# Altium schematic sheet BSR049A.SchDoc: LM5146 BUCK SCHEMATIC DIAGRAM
size 431 x 279 mm; Date: Not shown in title block; ApprovedBy: Not shown in title block; CheckedBy: Not shown in title block; Author: Not shown in title block; CompanyName: Not shown in title block; DrawnBy: K Nielson; Engineer: Not shown in title block; Organization: Not shown in title block; Address1: Not shown in title block; Address2: Not shown in title block; Address3: Not shown in title block; Address4: Not shown in title block; DocumentNumber: 1; Revision: Use project parameter SCH_Rev; SheetNumber: 1; SheetTotal: 2; PageSetup: Record=PageOptions¦CenterHorizontal=True¦CenterVertical=True¦PrintScale=0.96¦XCorrection=1.00¦YCorrection=1.00¦PrintKind=0¦BorderSize=5000000¦LeftOffset=0¦BottomOffset=0¦Orientation=2¦PaperLength=1000¦PaperWidth=1000¦Scale=100¦PaperSource=15¦PrintQuality=-3¦MediaType=1¦DitherType=10¦PrintScaleMode=1¦PaperKind=11x17¦PaperIndex=17
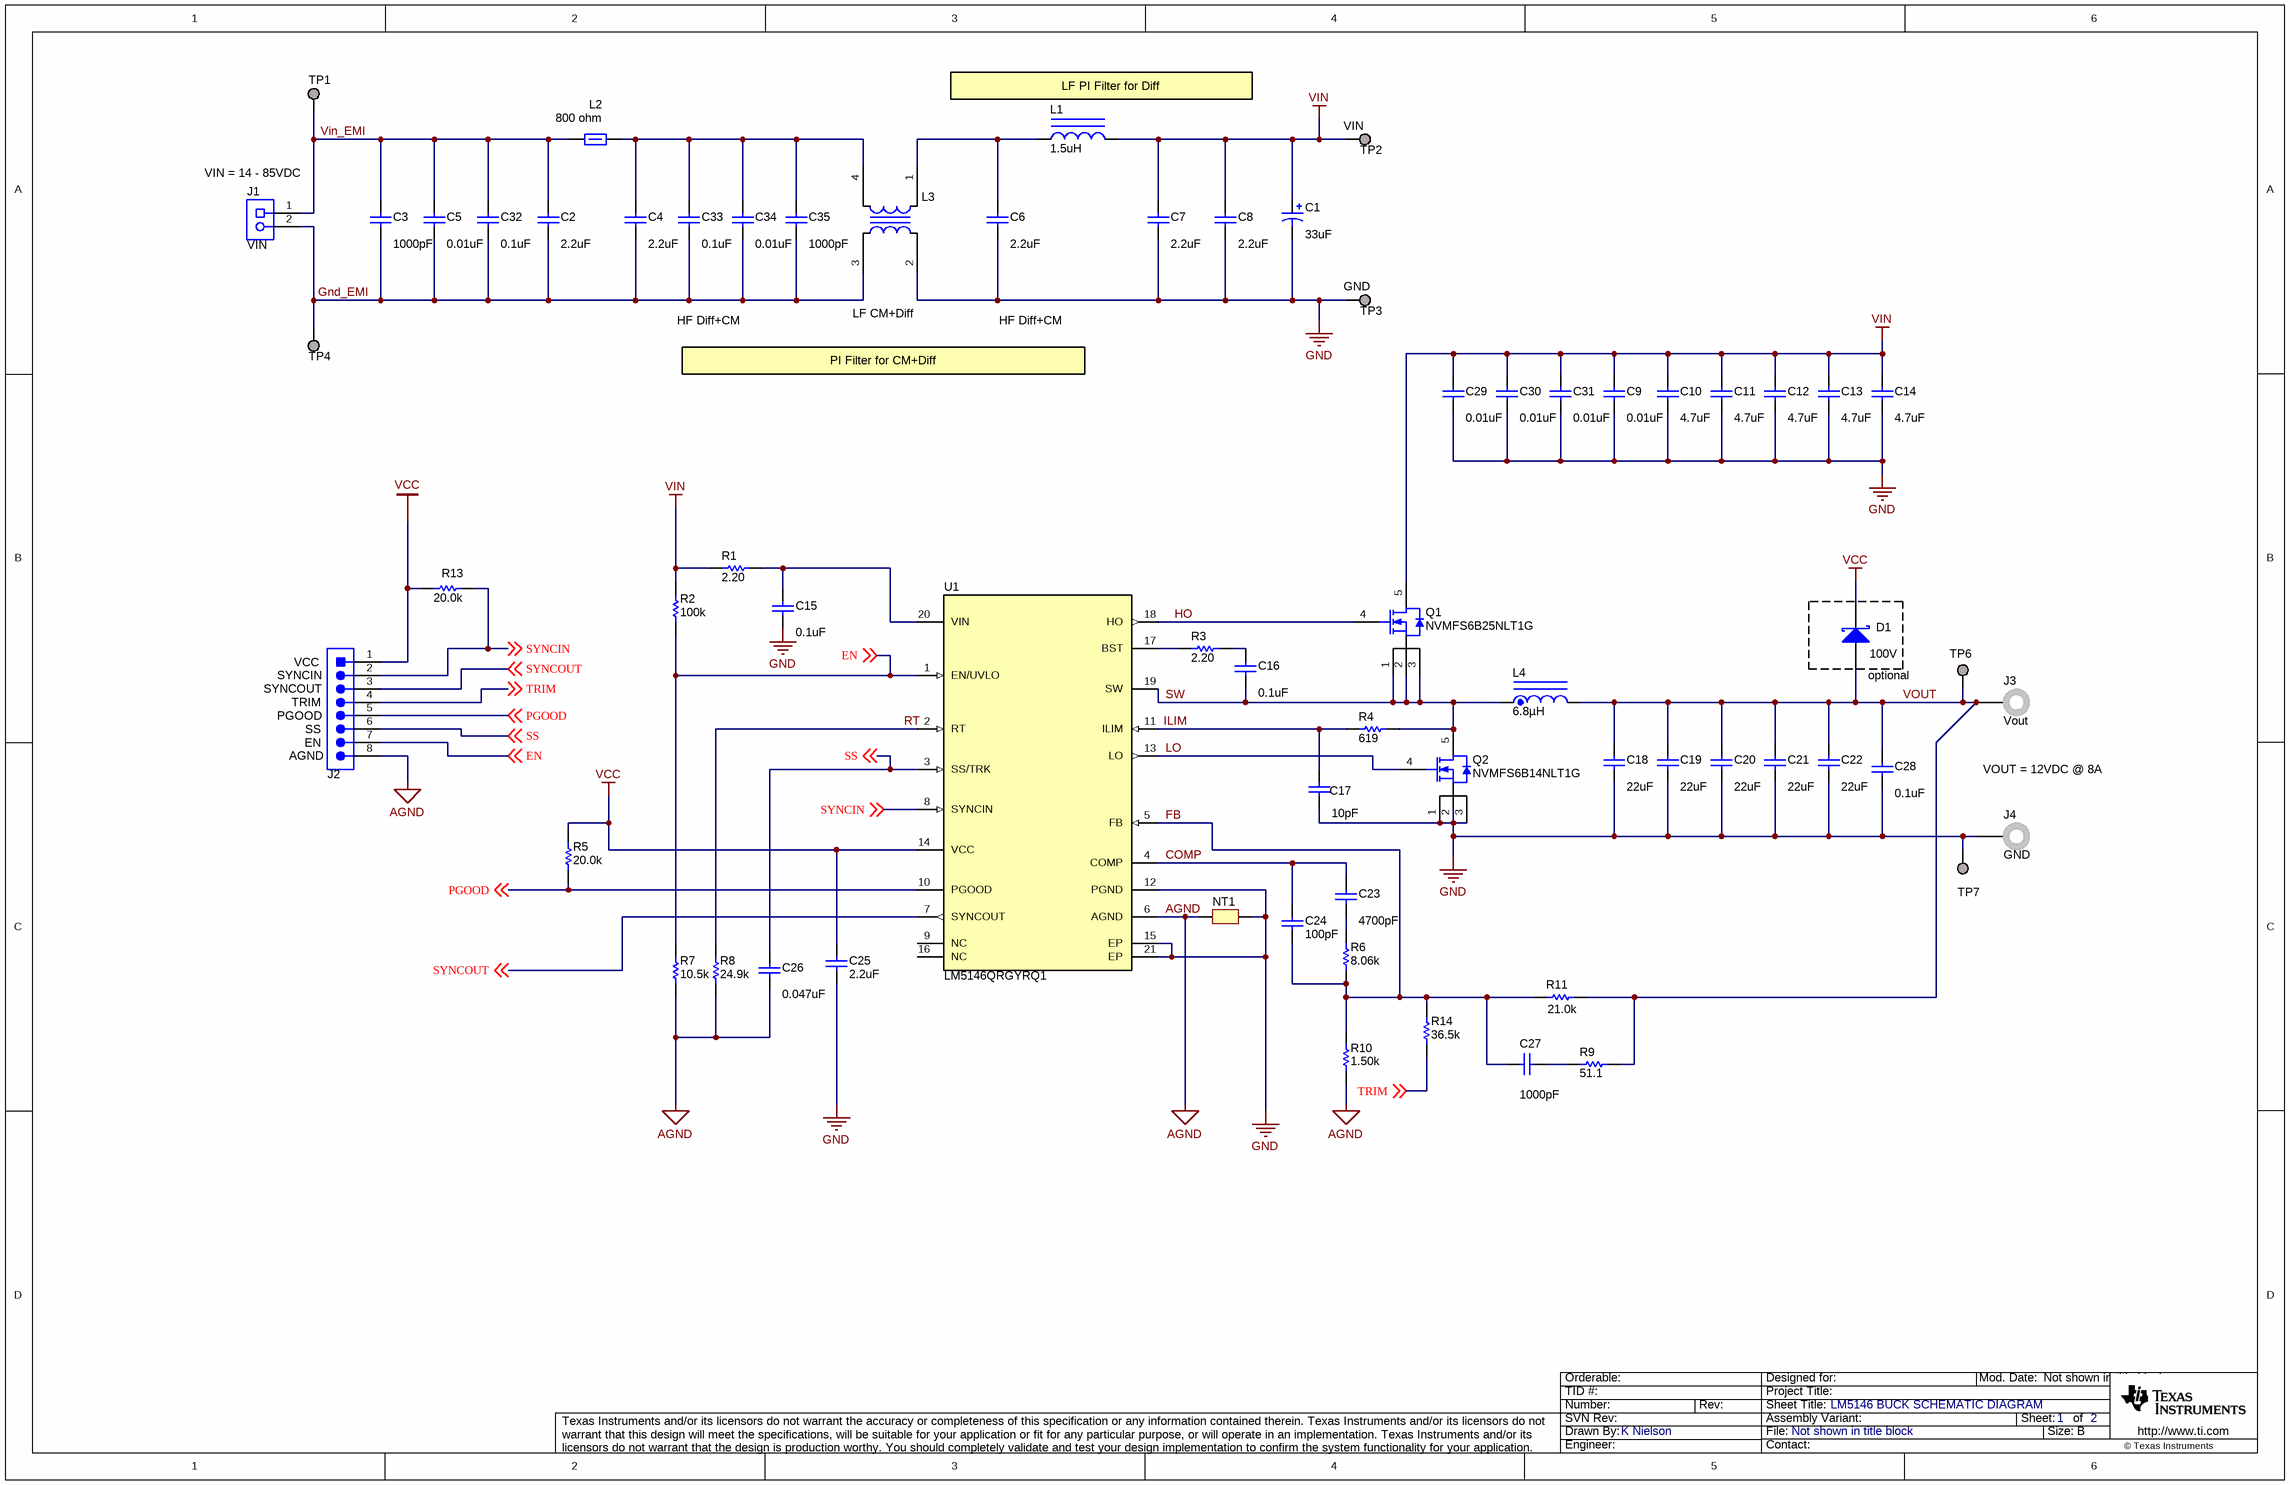
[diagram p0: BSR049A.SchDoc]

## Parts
C1  ValueDisplayed: 33uF  [SM_RADIAL_G]  (hidden comment: EEE-FK2A330P)
C2  ValueDisplayed: 2.2uF  [1210_250]  (hidden comment: CGA6N3X7R2A225K230AB)
C3  ValueDisplayed: 1000pF  [0603L]  (hidden comment: CGA3E2X7R2A102K080AA)
C4  ValueDisplayed: 2.2uF  [1210_250]  (hidden comment: CGA6N3X7R2A225K230AB)
C5  ValueDisplayed: 0.01uF  [0603L]  (hidden comment: GRM188R72A103KA01D)
C6  ValueDisplayed: 2.2uF  [1210_250]  (hidden comment: CGA6N3X7R2A225K230AB)
C7  ValueDisplayed: 2.2uF  [1210_250]  (hidden comment: CGA6N3X7R2A225K230AB)
C8  ValueDisplayed: 2.2uF  [1210_250]  (hidden comment: CGA6N3X7R2A225K230AB)
C9  ValueDisplayed: 0.01uF  [0603L]  (hidden comment: GRM188R72A103KA01D)
C10  ValueDisplayed: 4.7uF  [1210]  (hidden comment: C3225X7S2A475K200AE)
C11  ValueDisplayed: 4.7uF  [1210]  (hidden comment: C3225X7S2A475K200AE)
C12  ValueDisplayed: 4.7uF  [1210]  (hidden comment: C3225X7S2A475K200AE)
C13  ValueDisplayed: 4.7uF  [1210]  (hidden comment: C3225X7S2A475K200AE)
C14  ValueDisplayed: 4.7uF  [1210]  (hidden comment: C3225X7S2A475K200AE)
C15  ValueDisplayed: 0.1uF  [0603L]  (hidden comment: CGA3E3X7S2A104K080AB)
C16  ValueDisplayed: 0.1uF  [0603L]  (hidden comment: CGA3E3X7S2A104K080AB)
C17  ValueDisplayed: 10pF  [0603L]  (hidden comment: 885012006073)
C18  ValueDisplayed: 22uF  [1210_270]  (hidden comment: TMK325B7226KMHT)
C19  ValueDisplayed: 22uF  [1210_270]  (hidden comment: TMK325B7226KMHT)
C20  ValueDisplayed: 22uF  [1210_270]  (hidden comment: TMK325B7226KMHT)
C21  ValueDisplayed: 22uF  [1210_270]  (hidden comment: TMK325B7226KMHT)
C22  ValueDisplayed: 22uF  [1210_270]  (hidden comment: TMK325B7226KMHT)
C23  ValueDisplayed: 4700pF  [0402]  (hidden comment: GRM155R71C472KA01D)
C24  ValueDisplayed: 100pF  [0402]  (hidden comment: CGA2B2C0G1H101J050BA)
C25  ValueDisplayed: 2.2uF  [0805_HV]  (hidden comment: GRM21BR71E225KA73L)
C26  ValueDisplayed: 0.047uF  [0402]  (hidden comment: C1005X7R1C473K050BC)
C27  ValueDisplayed: 1000pF  [0402]  (hidden comment: CGA2B2X7R1H102K050BA)
C28  ValueDisplayed: 0.1uF  [0603L]  (hidden comment: CGA3E3X7S2A104K080AB)
C29  ValueDisplayed: 0.01uF  [0603L]  (hidden comment: GRM188R72A103KA01D)
C30  ValueDisplayed: 0.01uF  [0603L]  (hidden comment: GRM188R72A103KA01D)
C31  ValueDisplayed: 0.01uF  [0603L]  (hidden comment: GRM188R72A103KA01D)
C32  ValueDisplayed: 0.1uF  [0603L]  (hidden comment: CGA3E3X7S2A104K080AB)
C33  ValueDisplayed: 0.1uF  [0603L]  (hidden comment: CGA3E3X7S2A104K080AB)
C34  ValueDisplayed: 0.01uF  [0603L]  (hidden comment: GRM188R72A103KA01D)
C35  ValueDisplayed: 1000pF  [0603L]  (hidden comment: CGA3E2X7R2A102K080AA)
D1  100V  [SOD-523]
J1  VIN  [Phoenix_1984617]
J2  TSW-108-07-G-S  [TSW-108-07-G-S]  (value not drawn)
J3  Vout  [Keystone575-8]
J4  GND  [Keystone575-8]
L1  ValueDisplayed: 1.5uH  [VCMT063T]  (hidden comment: VCMT063T-1R5MN5)
L2  800 ohm  [2220_390]
L3  ACM12V-701-2PL-TL00  [TDK_ACM12V]  (value not drawn)
L4  ValueDisplayed: 6.8µH  [VCHA105D]  (hidden comment: VCHA105D-6R8MS6)
NT1  net tie  [Net-Tie_10mil]  (value not drawn)  (net tie, no BOM)
Q1  NVMFS6B25NLT1G  [SO-8FL]
Q2  NVMFS6B14NLT1G  [SO-8FL]
R1  ValueDisplayed: 2.20  [0603L]  (hidden comment: ERJ-3RQF2R2V)
R2  ValueDisplayed: 100k  [0603]  (hidden comment: CRCW0603100KFKEA)
R3  ValueDisplayed: 2.20  [0603L]  (hidden comment: ERJ-3RQF2R2V)
R4  ValueDisplayed: 619  [0402]  (hidden comment: CRCW0402619RFKED)
R5  ValueDisplayed: 20.0k  [0402]  (hidden comment: CRCW040220K0FKED)
R6  ValueDisplayed: 8.06k  [0402]  (hidden comment: CRCW04028K06FKED)
R7  ValueDisplayed: 10.5k  [0402]  (hidden comment: CRCW040210K5FKED)
R8  ValueDisplayed: 24.9k  [0402]  (hidden comment: CRCW040224K9FKED)
R9  ValueDisplayed: 51.1  [0402]  (hidden comment: CRCW040251R1FKED)
R10  ValueDisplayed: 1.50k  [0402]  (hidden comment: CRCW04021K50FKED)
R11  ValueDisplayed: 21.0k  [0402]  (hidden comment: CRCW040221K0FKED)
R13  ValueDisplayed: 20.0k  [0603L]  (hidden comment: CRCW060320K0FKEA)
R14  ValueDisplayed: 36.5k  [0402]  (hidden comment: CRCW040236K5FKED)
TP1  5017  [Keystone_5017]  (value not drawn)
TP2  VIN  [Keystone_5017]
TP3  GND  [Keystone_5017]
TP4  GND  [Keystone_5017]  (value not drawn)
TP6  GND  [Keystone_5017]  (value not drawn)
TP7  GND  [Keystone_5017]  (value not drawn)
U1  LM5146QRGYRQ1  [RGY0020B]

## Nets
AGND: C26.1 J2.8 NT1.1 R7.1 R8.2 R10.1 U1.6(AGND)
GND: C1.2(-) C6.2 C7.2 C8.2 C9.2 C10.2 C11.2 C12.2 C13.2 C14.2 C15.2 C17.2 C18.2 C19.2 C20.2 C21.2 C22.2 C25.2 C28.2 C29.2 C30.2 C31.2 J4.1 L3.2 NT1.2 Q2.1(S) Q2.2(S) Q2.3(S) TP3.1 TP7.1 U1.12(PGND) U1.15(EP) U1.21(EP)
VCC: C25.1 D1.1(K) J2.1 R5.1 R13.1 U1.14(VCC)
VIN: C1.1(+) C7.1 C8.1 C9.1 C10.1 C11.1 C12.1 C13.1 C14.1 C29.1 C30.1 C31.1 L1.2 Q1.5(D) R1.1 R2.1 TP2.1
COMP: C23.1 C24.1 U1.4(COMP)
EN: J2.7 R2.2 R7.2 U1.1(EN/UVLO) ; off-sheet EN
FB: C24.2 C27.2 R6.1 R10.2 R11.2 R14.2 U1.5(FB)
Gnd_EMI: C2.2 C3.2 C4.2 C5.2 C32.2 C33.2 C34.2 C35.2 J1.2 L3.3 TP4.1
HO: Q1.4(G) U1.18(HO)
ILIM: C17.1 R4.1 U1.11(ILIM)
LO: Q2.4(G) U1.13(LO)
PGOOD: J2.5 R5.2 U1.10(PGOOD) ; off-sheet PGOOD
RT: R8.1 U1.2(RT)
SS: C26.2 J2.6 U1.3(SS/TRK) ; off-sheet SS
SW: C16.2 L4.1 Q1.1(S) Q1.2(S) Q1.3(S) Q2.5(D) R4.2 U1.19(SW)
SYNCIN: J2.2 R13.2 U1.8(SYNCIN) ; off-sheet SYNCIN
SYNCOUT: J2.3 U1.7(SYNCOUT) ; off-sheet SYNCOUT
TRIM: J2.4 R14.1 ; off-sheet TRIM
Vin_EMI: C2.1 C3.1 C5.1 C32.1 J1.1 L2.1 TP1.1
VOUT: C18.1 C19.1 C20.1 C21.1 C22.1 C28.1 D1.2(A) J3.1 L4.2 R9.1 R11.1 TP6.1
NetC4_1: C4.1 C33.1 C34.1 C35.1 L2.2 L3.4
NetC6_1: C6.1 L1.1 L3.1
NetC15_1: C15.1 R1.2 U1.20(VIN)
NetC16_1: C16.1 R3.2
NetC23_2: C23.2 R6.2
NetC27_1: C27.1 R9.2
NetR3_1: R3.1 U1.17(BST)

Not connected (* = marked no-connect by the designer): U1 9(NC) 16(NC)

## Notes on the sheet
- (near L1) LF PI Filter for Diff
- (near J1) VIN = 14 - 85VDC
- HF Diff+CM
- LF CM+Diff
- PI Filter for CM+Diff
- (near J2) SYNCOUT
- (near J2) SYNCIN
- (near J2) VCC
- (near J2) TRIM
- (near D1) optional
- (near J2) PGOOD
- (near J2) AGND
- (near J2) SS
- (near J2) EN
- VOUT = 12VDC @ 8A

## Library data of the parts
C1 = CMP-0011203-2: CAP, AL, 33 uF, 100 V, +/- 20%, 0.7 ohm, AEC-Q200 Grade 2, SMD; Manufacturer: Panasonic; Cap_F: 33µF; IRMS_A: 2dA; SizeAreaWB_mm2: 172.2; SizeArea_mm2: 123.6; AEC Qualified: Y; AEC Category: Q200; Value: 33uF; TaMax_C: 105°C; SizeZ_mm: 10.2; AEC Grade: 2; TaMin_C: -55°C; VDC_V: 100V; SizeY_mm: 10.3; U/M: EA; Value1: 0.7 ohm; CompType: Capacitor; SizeX_mm: 12; ESR_ohm: 7d; Cap_Case: G
C2 C4 = CMP-0009152-2: CAP, CERM, 2.2 uF, 100 V, +/- 10%, X7R, AEC-Q200 Grade 1,; Manufacturer: TDK; TaMin_C: -55°C; Polarized: N; SizeAreaWB_mm2: 14.7; Value1: 0.00173 ohm; U/M: EA; Value: 2.2uF; TaMax_C: 125°C; SizeZ_mm: 2.5; SizeX_mm: 3.2; Value2: 100V; SizeArea_mm2: 8; CompType: Capacitor; AEC Qualified: Y; Cap_F: 2.2µF; AEC Grade: 1; AEC Category: Q200; ESR_ohm: 1.73m; IRMS_A: 5.59317A
C3 C35 = CMP-0007081-4: CAP, CERM, 1000 pF, 100 V, +/- 10%, X7R, AEC-Q200 Grade 1, 0603; Manufacturer: TDK; TaMin_C: -55°C; ESR_ohm: 1.97137; Polarized: N; SizeAreaWB_mm2: 4.68; Value1: 1.97137 ohm; U/M: EA; Value: 1000pF; TaMax_C: 125°C; SizeZ_mm: 1; SizeX_mm: 1.6; SizeY_mm: 0.8; Cap_Case: 0603; Value2: 100V; SizeArea_mm2: 1.28; CompType: Capacitor; AEC Qualified: Y; Cap_F: 1nF; IRMS_A: 3.05705dA; AEC Category: Q200
C5 C29-C31 C34 = CMP-0007468-5: CAP, CERM, 0.01 uF, 100 V, +/- 10%, X7R, 0603; Manufacturer: MuRata; TaMin_C: -55°C; Polarized: N; SizeAreaWB_mm2: 4.68; Value1: Unknown; U/M: EA; Value: 0.01uF; TaMax_C: 125°C; SizeZ_mm: 1; SizeX_mm: 1.6; SizeY_mm: 0.8; Cap_Case: 0603; Value2: 100V; SizeArea_mm2: 1.28; CompType: Capacitor; Cap_F: 10nF; AEC Category: Q200
C6-C8 = CMP-0009152-2: CAP, CERM, 2.2 uF, 100 V, +/- 10%, X7R, AEC-Q200 Grade 1,; Manufacturer: TDK; TaMin_C: -55°C; Polarized: N; SizeAreaWB_mm2: 14.7; Value1: 0.00173 ohm; U/M: EA; Value: 2.2uF; TaMax_C: 125°C; SizeZ_mm: 2.5; SizeX_mm: 3.2; Value2: 100V; SizeArea_mm2: 8; AEC Qualified: Y; Cap_F: 2.2µF; AEC Grade: 1; AEC Category: Q200; ESR_ohm: 1.73m; IRMS_A: 5.59317A
C9 = CMP-0007468-5: CAP, CERM, 0.01 uF, 100 V, +/- 10%, X7R, 0603; Manufacturer: MuRata; TaMin_C: -55°C; Polarized: N; SizeAreaWB_mm2: 4.68; Value1: Unknown; U/M: EA; Value: 0.01uF; TaMax_C: 125°C; SizeZ_mm: 1; SizeX_mm: 1.6; SizeY_mm: 0.8; Cap_Case: 0603; Value2: 100V; SizeArea_mm2: 1.28; Cap_F: 10nF; AEC Category: Q200
C10 C12-C14 = CMP-0009135-2: CAP, CERM, 4.7 uF, 100 V, +/- 10%, X7S, 1210; Manufacturer: TDK; TaMin_C: -55°C; Polarized: N; SizeAreaWB_mm2: 14.7; Value1: Unknown; U/M: EA; Value: 4.7uF; TaMax_C: 125°C; SizeZ_mm: 1.35; SizeX_mm: 3.2; SizeY_mm: 2.5; Value2: 100V; SizeArea_mm2: 8; CompType: Capacitor; Cap_F: 4.7µF; AEC Category: Q200
C11 = CMP-0009135-2: CAP, CERM, 4.7 uF, 100 V, +/- 10%, X7S, 1210; Manufacturer: TDK; TaMin_C: -55°C; Polarized: N; SizeAreaWB_mm2: 14.7; Value1: Unknown; U/M: EA; Value: 4.7uF; TaMax_C: 125°C; SizeZ_mm: 1.35; SizeX_mm: 3.2; SizeY_mm: 2.5; Value2: 100V; SizeArea_mm2: 8; Cap_F: 4.7µF; AEC Category: Q200
C15 C16 C28 C32 C33 = CMP-0007099-4: CAP, CERM, 0.1 uF, 100 V, +/- 10%, X7S, AEC-Q200 Grade 1, 0603; Manufacturer: TDK; TaMin_C: -55°C; ESR_ohm: 0.04959; Polarized: N; SizeAreaWB_mm2: 4.68; Value1: 0.04959 ohm; U/M: EA; Value: 0.1uF; TaMax_C: 125°C; SizeZ_mm: 1; SizeX_mm: 1.6; SizeY_mm: 0.8; Cap_Case: 0603; Value2: 100V; SizeArea_mm2: 1.28; CompType: Capacitor; AEC Qualified: Y; Cap_F: 100nF; IRMS_A: 7.51618dA; AEC Category: Q200
C17 = CMP-0078152-1: CAP, CERM, 10 pF, 100 V,+/- 5%, C0G/NP0, 0603; Manufacturer: Wurth Elektronik; TaMin_C: -55°C; Polarized: N; SizeAreaWB_mm2: 4.68; U/M: EA; Value: 10pF; TaMax_C: 125°C; SizeZ_mm: 1; SizeX_mm: 1.6; SizeY_mm: 0.8; Cap_Case: 0603; Value2: 100V; SizeArea_mm2: 1.28; CompType: Capacitor; AEC Category: Q200
C18 = CMP-0009255-2: CAP, CERM, 22 uF, 25 V, +/- 10%, X7R, AEC-Q200 Grade 1, 1210; Manufacturer: Taiyo Yuden; TaMin_C: -55°C; Polarized: N; SizeAreaWB_mm2: 14.7; Value1: Unknown; U/M: EA; Value: 22uF; TaMax_C: 125°C; SizeZ_mm: 2.7; SizeX_mm: 3.2; SizeY_mm: 2.5; Cap_Case: 1210; Value2: 25V; SizeArea_mm2: 8; CompType: Capacitor; AEC Qualified: Y; Cap_F: 22µF; AEC Grade: 1; AEC Category: Q200
C19-C22 = CMP-0009255-2: CAP, CERM, 22 uF, 25 V, +/- 10%, X7R, AEC-Q200 Grade 1, 1210; Manufacturer: Taiyo Yuden; TaMin_C: -55°C; Polarized: N; SizeAreaWB_mm2: 14.7; Value1: Unknown; U/M: EA; Value: 22uF; TaMax_C: 125°C; SizeZ_mm: 2.7; SizeX_mm: 3.2; SizeY_mm: 2.5; Cap_Case: 1210; Value2: 25V; SizeArea_mm2: 8; AEC Qualified: Y; Cap_F: 22µF; AEC Grade: 1; AEC Category: Q200
C23 = CMP-0006652-2: CAP, CERM, 4700 pF, 16 V, +/- 10%, X7R, 0402; Manufacturer: MuRata; TaMin_C: -55°C; Polarized: N; SizeAreaWB_mm2: 3; Value1: Unknown; U/M: EA; Value: 4700pF; TaMax_C: 125°C; SizeZ_mm: 0.6; SizeX_mm: 1; SizeY_mm: 0.5; Value2: 16V; Cap_F: 4.7nF; AEC Category: Q200
C24 = CMP-0006308-2: CAP, CERM, 100 pF, 50 V, +/- 5%, C0G/NP0, AEC-Q200 Grade 1, 0402; Manufacturer: TDK; Polarized: N; Value: 100pF; U/M: EA; Value1: Unknown; VDC_V: 50V; TaMin_C: -55°C; TaMax_C: 125°C; SizeArea_mm2: 0.5; SizeAreaWB_mm2: 3; SizeX_mm: 1; SizeZ_mm: 0.6; AEC Category: Q200; AEC Qualified: Y
C25 = CMP-0008342-2: CAP, CERM, 2.2 uF, 25 V, +/- 10%, X7R, 0805; Manufacturer: MuRata; Polarized: N; CompType: Capacitor; Value: 2.2uF; U/M: EA; Cap_F: 2.2µF; ESR_ohm: 5m; Value1: 0.005 ohm; VDC_V: 25V; TaMin_C: -55°C; TaMax_C: 125°C; Cap_Case: 0805; SizeArea_mm2: 2.5; SizeAreaWB_mm2: 6.75; SizeX_mm: 2; SizeY_mm: 1.25; SizeZ_mm: 1.45; AEC Category: Q200
C26 = CMP-0006294-2: CAP, CERM, 0.047 uF, 16 V, +/- 10%, X7R, 0402; Manufacturer: TDK; Value1: 0.0305 ohm; SizeZ_mm: 0.6; SizeX_mm: 1; SizeY_mm: 0.5; Value2: 16V; AEC Qualified: N; AEC Category: Q200; TaMin_C: -55°C; ESR_ohm: 0.0305; SizeAreaWB_mm2: 3; U/M: EA; TaMax_C: 125°C; Cap_F: 47nF
C27 = CMP-0006314-2: CAP, CERM, 1000 pF, 50 V, +/- 10%, X7R, AEC-Q200 Grade 1, 0402; Manufacturer: TDK; Value: 1000pF; SizeZ_mm: 0.6; SizeX_mm: 1; SizeY_mm: 0.5; Value2: 50V; AEC Qualified: Y; AEC Category: Q200; Value1: 2.25564 ohm; TaMin_C: -55°C; Polarized: N; SizeAreaWB_mm2: 3; U/M: EA; TaMax_C: 125°C; Cap_F: 1nF; ESR_ohm: 2.25564; IRMS_A: 2.80466dA
D1 = CMP-0028894-2: Diode, Schottky, 100 V, 0.2 A, SOD-523; Manufacturer: STMicroelectronics; PartNumber: BAT41KFILM; Io_A: 2dA; Green_Lifecycle: Not Set; SizeAreaWB_mm2: 5.13; Green_REACh: Incomplete; TJmax_C: 150°C; U/M: EA; SizeZ_mm: 0.65; SizeX_mm: 1.7; SizeY_mm: 0.9; Vf_V: 1V; SizeArea_mm2: 1.53; Value1: 0.2A; AEC Qualified: N; AEC Category: Q101
J1 = CMP-0055519-1: Terminal Block, 3.5mm, 2x1, TH; Manufacturer: Phoenix Contact; PartNumber: 1984617; CNHeader: FALSE; Current_A: 17.5A; Gender: Female; Cert_CULUS: Y; Voltage_V: 200V; Row_Count: 1; Pitch_mm: 3.5; CT: TRUE
J2 = CMP-0075419-1: Header, 100mil, 8x1, Gold, TH; Manufacturer: Samtec; Pitch_mm: 2.54; Cert_VDE: N; Gender: Male; Cert_CSA: Y; Voltage_V: 550V; Green_REACh: Passed; Current_A: 6.3A; CT: False; Green_Lifecycle: Active; Row_Count: 1; CNHeader: True
J3 J4 = CMP-0055166-2: Standard Banana Jack, Uninsulated, 8.9mm; PartNumber: 575-8; Manufacturer: Keystone; Green_REACh: Passed; CT: TRUE; Green_Lifecycle: Active; CNHeader: FALSE
L1 = CMP-0059934-1: Inductor, Drum Core, Powdered Iron, 1.5 uH, 9 A, 0.0125 ohm, AEC-Q200 Grade 0, SMD; Manufacturer: Cyntec; Isat: 9A @ 20% inductance drop; Irms: 10.5A @ 40C rise; SizeAreaWB_mm2: 76.97; DCR_ohm: 0.0125; Value: 1.5uH; Imax_A: 9A; SizeZ_mm: 3; SizeX_mm: 6.95; SizeY_mm: 6.6; SizeArea_mm2: 45.87; Ind_H: 1.5µH; AEC Qualified: Y; AEC Grade: 0; AEC Category: Q200
L2 = CMP-0003396-1: Ferrite Bead, 800 ohm @ 100 MHz, 8 A, 2220; Manufacturer: Laird-Signal Integrity Products; PartNumber: HR2220V801R-10; Ztyp@1GHz_Ohm: 75; ZTyp@100MHz_Ohm: 800; SizeAreaWB_mm2: 53.96; DCR_ohm: 0.01; Value1: 0.01 ohm; Imax_A: 8A; SizeZ_mm: 3.9; SizeX_mm: 5.6; SizeY_mm: 5.1; SizeArea_mm2: 28.56
L3 = CMP-0084691-1: Coupled inductor,  ohm, AEC-Q200 Grade 1, SMD; Manufacturer: TDK; SizeAreaWB_mm2: 182; SizeZ_mm: 6; SizeX_mm: 12; SizeY_mm: 11; SizeArea_mm2: 132; AEC Grade: 1; AEC Category: Q200; AEC Qualified: Y
L4 = CMP-0082255-1: Inductor, Drum Core, Powdered Iron, 6.8 µH, 10.8 A, 0.014 ohm, AEC-Q200 Grade 0, SMD; Manufacturer: Cyntec; Isat: 11.4A @ 30% inductance drop; Irms: 10.8A @ 40C rise; SizeAreaWB_mm2: 154.2; DCR_ohm: 0.014; Value: 6.8uH; Imax_A: 10.8A; SizeZ_mm: 5.4; SizeX_mm: 10.85; SizeY_mm: 10; SizeArea_mm2: 108.5; AEC Qualified: Y; AEC Grade: 0; AEC Category: Q200
NT1 = CMP-0078142-2: Single point connection between nets.; CompType: Net-Tie
Q1 = CMP-0082014-2: MOSFET, N-CH, 100 V, 8 A, AEC-Q101, SO-8FL; Manufacturer: ON Semiconductor; Alternate Manufacturer: None; ChType: N; QgTyp_nC: 6.4; SizeAreaWB_mm2: 58.2725; SizeArea_mm2: 31.6725; IdsMax_A: 8A; AEC Qualified: Y; VdsMax_V: 100V; Rdson45_ohm: 0.039; Vgs_V: 16V; AEC Category: Q101; Value: 100V; SizeZ_mm: 1.1; SizeY_mm: 5.15; Value2: 6.4 nC; Value1: 0.039 ohm; SizeX_mm: 6.15; ChMode: Enhancement
Q2 = CMP-0081522-2: MOSFET, N-CH, 100 V, 11 A, AEC-Q101, SO-8FL; Manufacturer: ON Semiconductor; Alternate Manufacturer: None; ChType: N; QgTyp_nC: 8; SizeAreaWB_mm2: 58.2725; SizeArea_mm2: 31.6725; IdsMax_A: 11A; AEC Qualified: Y; VdsMax_V: 100V; Rdson45_ohm: 0.019; Vgs_V: 16V; AEC Category: Q101; Value: 100V; SizeZ_mm: 1; SizeY_mm: 6.15; Value2: 8 nC; Value1: 0.019 ohm; SizeX_mm: 5.15; ChMode: Enhancement
R1 R3 = CMP-0022711-2: RES, 2.20, 1%, 0.1 W, 0603; Manufacturer: Panasonic; Power_W: 100mW; TempCo: 200 ppm/C; Value_Code: 2R20; Value: 2.20; Res_ohm: 2.2; SizeX_mm: 1.6; SizeY_mm: 0.8; SizeZ_mm: 1; Value2: 0.1W; SizeArea_mm2: 1.28; CompType: Resistor; AEC Category: Q200; U/M: EA
R2 = CMP-0021990-4: RES, 100 k, 1%, 0.1 W, AEC-Q200 Grade 0, 0603; Manufacturer: Vishay-Dale; Power_W: 100mW; TempCo: 100 ppm/C; Value: 100k; EIA_Code: E96; SizeX_mm: 1.6; SizeY_mm: 0.8; SizeZ_mm: 1; Value2: 0.1W; SizeArea_mm2: 1.28; AEC Qualified: Y; VDC_V: 75V; AEC Grade: 0; AEC Category: Q200
R4 = CMP-0026489-2: RES, 619, 1%, 0.063 W, AEC-Q200 Grade 0, 0402; Manufacturer: Vishay-Dale; Power_W: 63mW; TempCo: 100 ppm/C; Value_Code: 619R; Value: 619; EIA_Code: E96; SizeX_mm: 1; SizeY_mm: 0.5; SizeZ_mm: 0.6; Value2: 0.063W; AEC Qualified: Y; AEC Grade: 0; AEC Category: Q200; VDC_V: 50V
R5 = CMP-0026162-2: RES, 20.0 k, 1%, 0.063 W, AEC-Q200 Grade 0, 0402; Manufacturer: Vishay-Dale; Power_W: 63mW; TempCo: 100 ppm/C; Value_Code: 20k0; Value: 20.0k; EIA_Code: E96; Res_ohm: 20k; SizeX_mm: 1; SizeY_mm: 0.5; SizeZ_mm: 0.6; Value2: 0.063W; AEC Qualified: Y; VDC_V: 50V; AEC Category: Q200; AEC Grade: 0
R6 = CMP-0026588-2: RES, 8.06 k, 1%, 0.063 W, AEC-Q200 Grade 0, 0402; Manufacturer: Vishay-Dale; Power_W: 63mW; TempCo: 100 ppm/C; Value_Code: 8k06; Value: 8.06k; EIA_Code: E96; SizeX_mm: 1; SizeY_mm: 0.5; SizeZ_mm: 0.6; Value2: 0.063W; AEC Qualified: Y; VDC_V: 50V; AEC Category: Q200; AEC Grade: 0
R7 = CMP-0025960-3: RES, 10.5 k, 1%, 0.063 W, AEC-Q200 Grade 0, 0402; Manufacturer: Vishay-Dale; Power_W: 63mW; TempCo: 100 ppm/C; Value_Code: 10k5; Value: 10.5k; EIA_Code: E96; SizeX_mm: 1; SizeY_mm: 0.5; SizeZ_mm: 0.6; Value2: 0.063W; CompType: Resistor; AEC Qualified: Y; AEC Grade: 0; AEC Category: Q200; VDC_V: 50V
R8 = CMP-0026196-2: RES, 24.9 k, 1%, 0.063 W, AEC-Q200 Grade 0, 0402; Manufacturer: Vishay-Dale; Power_W: 63mW; TempCo: 100 ppm/C; Value_Code: 24k9; Value: 24.9k; EIA_Code: E96; SizeX_mm: 1; SizeY_mm: 0.5; SizeZ_mm: 0.6; Value2: 0.063W; AEC Qualified: Y; VDC_V: 50V; AEC Category: Q200; AEC Grade: 0
R9 = CMP-0026438-2: RES, 51.1, 1%, 0.063 W, AEC-Q200 Grade 0, 0402; Manufacturer: Vishay-Dale; Power_W: 63mW; TempCo: 100 ppm/C; Value_Code: 51R1; Value: 51.1; EIA_Code: E96; SizeX_mm: 1; SizeY_mm: 0.5; SizeZ_mm: 0.6; Value2: 0.063W; AEC Qualified: Y; VDC_V: 50V; AEC Grade: 0; AEC Category: Q200
R10 = CMP-0026088-3: RES, 1.50 k, 1%, 0.063 W, AEC-Q200 Grade 0, 0402; Manufacturer: Vishay-Dale; Power_W: 63mW; TempCo: 100 ppm/C; Value_Code: 1k50; Value: 1.50k; EIA_Code: E96; Res_ohm: 1.5k; SizeX_mm: 1; SizeY_mm: 0.5; SizeZ_mm: 0.6; Value2: 0.063W; AEC Qualified: Y; VDC_V: 50V; AEC Category: Q200; AEC Grade: 0
R11 = CMP-0026170-2: RES, 21.0 k, 1%, 0.063 W, AEC-Q200 Grade 0, 0402; Manufacturer: Vishay-Dale; Power_W: 63mW; TempCo: 100 ppm/C; Value_Code: 21k0; Value: 21.0k; EIA_Code: E96; Res_ohm: 21k; SizeX_mm: 1; SizeY_mm: 0.5; SizeZ_mm: 0.6; Value2: 0.063W; AEC Qualified: Y; VDC_V: 50V; AEC Category: Q200; AEC Grade: 0
R13 = CMP-0022204-4: RES, 20.0 k, 1%, 0.1 W, AEC-Q200 Grade 0, 0603; Manufacturer: Vishay-Dale; Power_W: 100mW; TempCo: 100 ppm/C; Value_Code: 20k0; Value: 20.0k; EIA_Code: E96; Res_ohm: 20k; SizeX_mm: 1.6; SizeY_mm: 0.8; SizeZ_mm: 1; Value2: 0.1W; SizeArea_mm2: 1.28; CompType: Resistor; AEC Qualified: Y; VDC_V: 75V; AEC Category: Q200; AEC Grade: 0
R14 = CMP-0026315-2: RES, 36.5 k, 1%, 0.063 W, AEC-Q200 Grade 0, 0402; Manufacturer: Vishay-Dale; Power_W: 63mW; TempCo: 100 ppm/C; Value_Code: 36k5; Value: 36.5k; EIA_Code: E96; SizeX_mm: 1; SizeY_mm: 0.5; SizeZ_mm: 0.6; Value2: 0.063W; AEC Qualified: Y; VDC_V: 50V; AEC Category: Q200; AEC Grade: 0
TP1 = CMP-0078225-1: PC Test Point, SMT; Manufacturer: Keystone
TP2-TP4 TP6 TP7 = CMP-0078225-1: PC Test Point, SMT; PartNumber: 5017; Manufacturer: Keystone
U1 = CMP-0081848-1: 5.5-V to 100-V Synchronous Buck Controller With Wide Duty Cycle Range, RGY0020B (VQFN-20); Alternate PartNumber: LM5146QRGYTQ1; Alternate Manufacturer: Texas Instruments; SizeAreaWB_mm2: 24.75; SizeZ_mm: 1; SizeX_mm: 3.5; SizeY_mm: 4.5; SizeArea_mm2: 15.75; CompType: IC; AEC Qualified: Y; AEC Category: Q200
